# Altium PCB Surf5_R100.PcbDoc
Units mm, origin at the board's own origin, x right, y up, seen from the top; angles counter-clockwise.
Board outline 75 x 21 mm, 4 copper layers (Top Layer, Internal Plane 1, Internal Plane 2, Bottom Layer), stack 0.603 mm thick; 72 components, 94 nets, 353 pads, 156 vias.
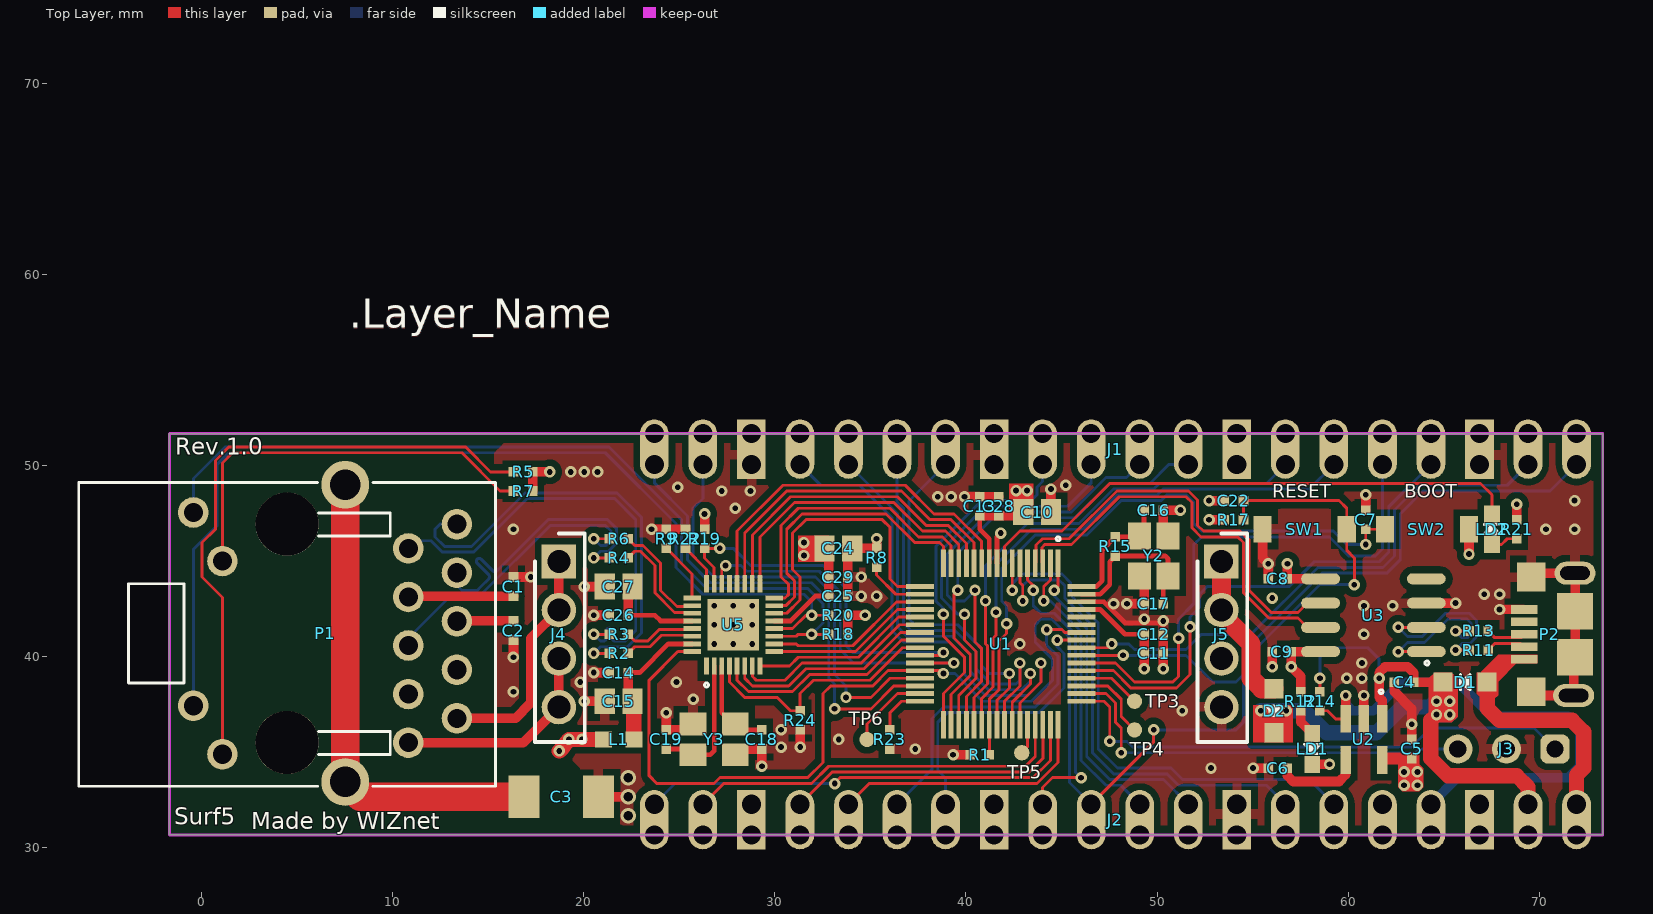
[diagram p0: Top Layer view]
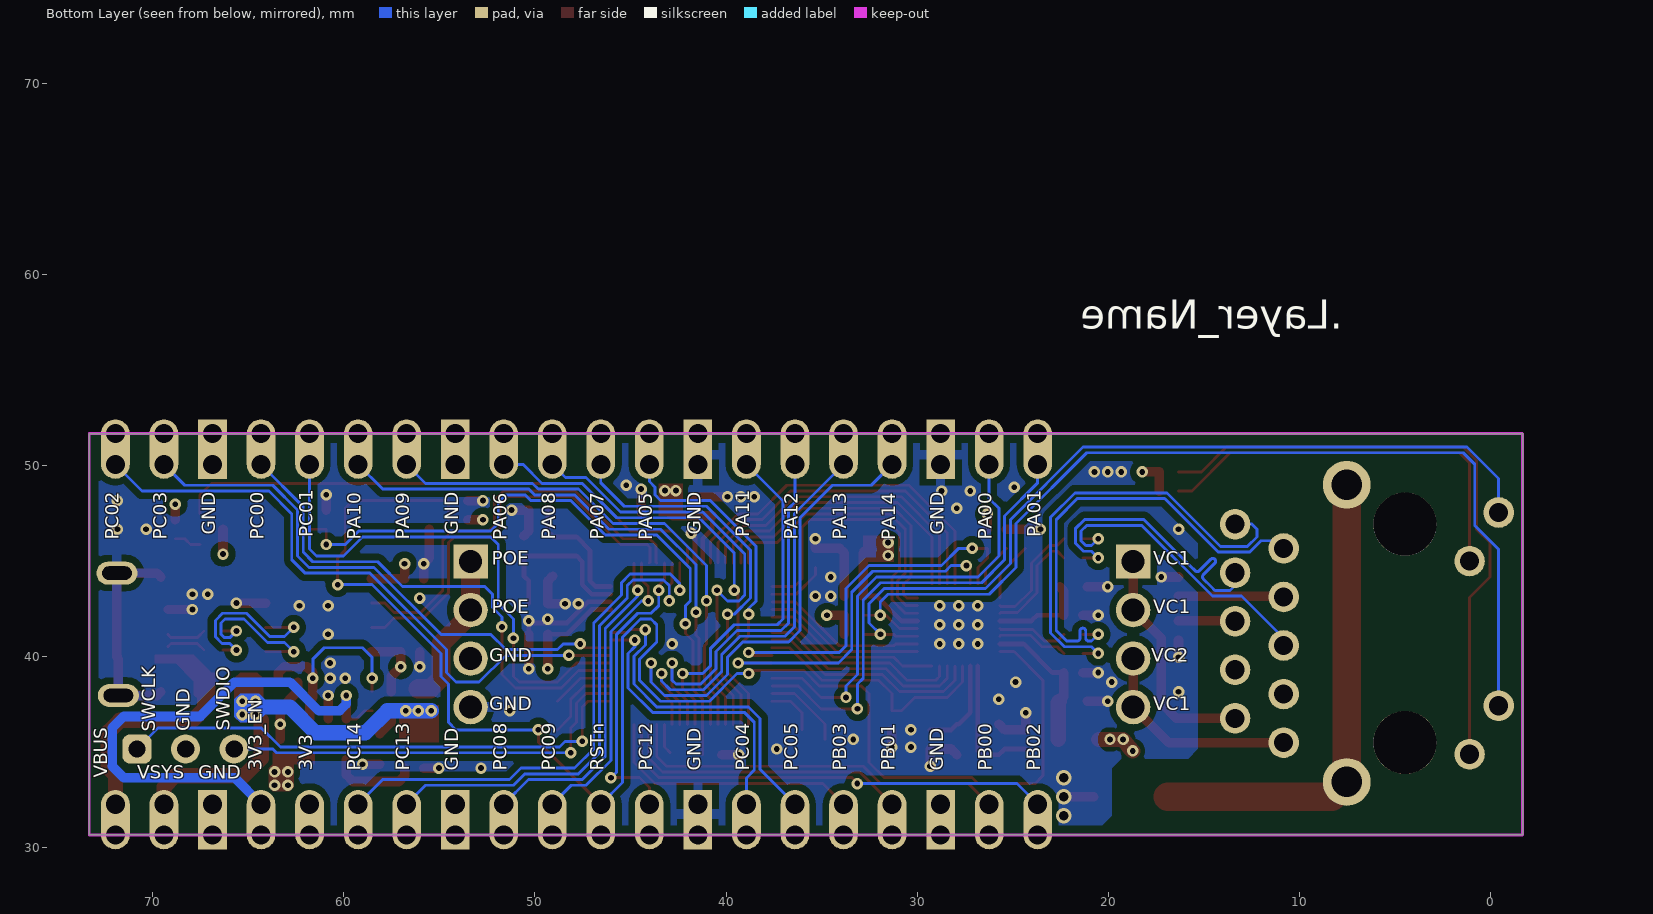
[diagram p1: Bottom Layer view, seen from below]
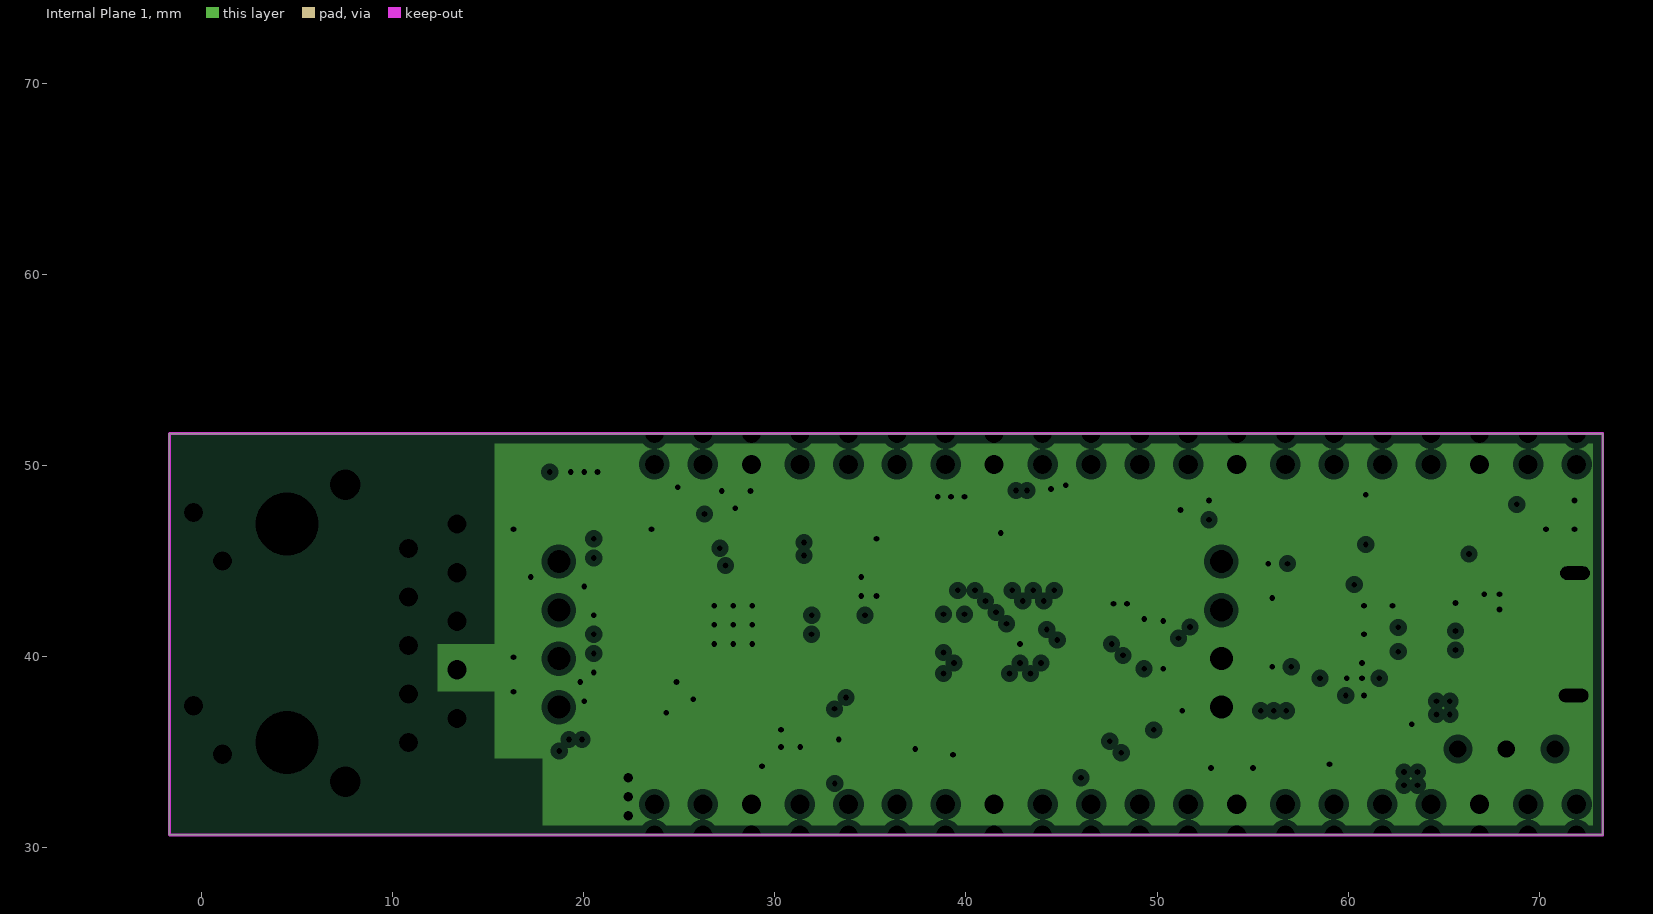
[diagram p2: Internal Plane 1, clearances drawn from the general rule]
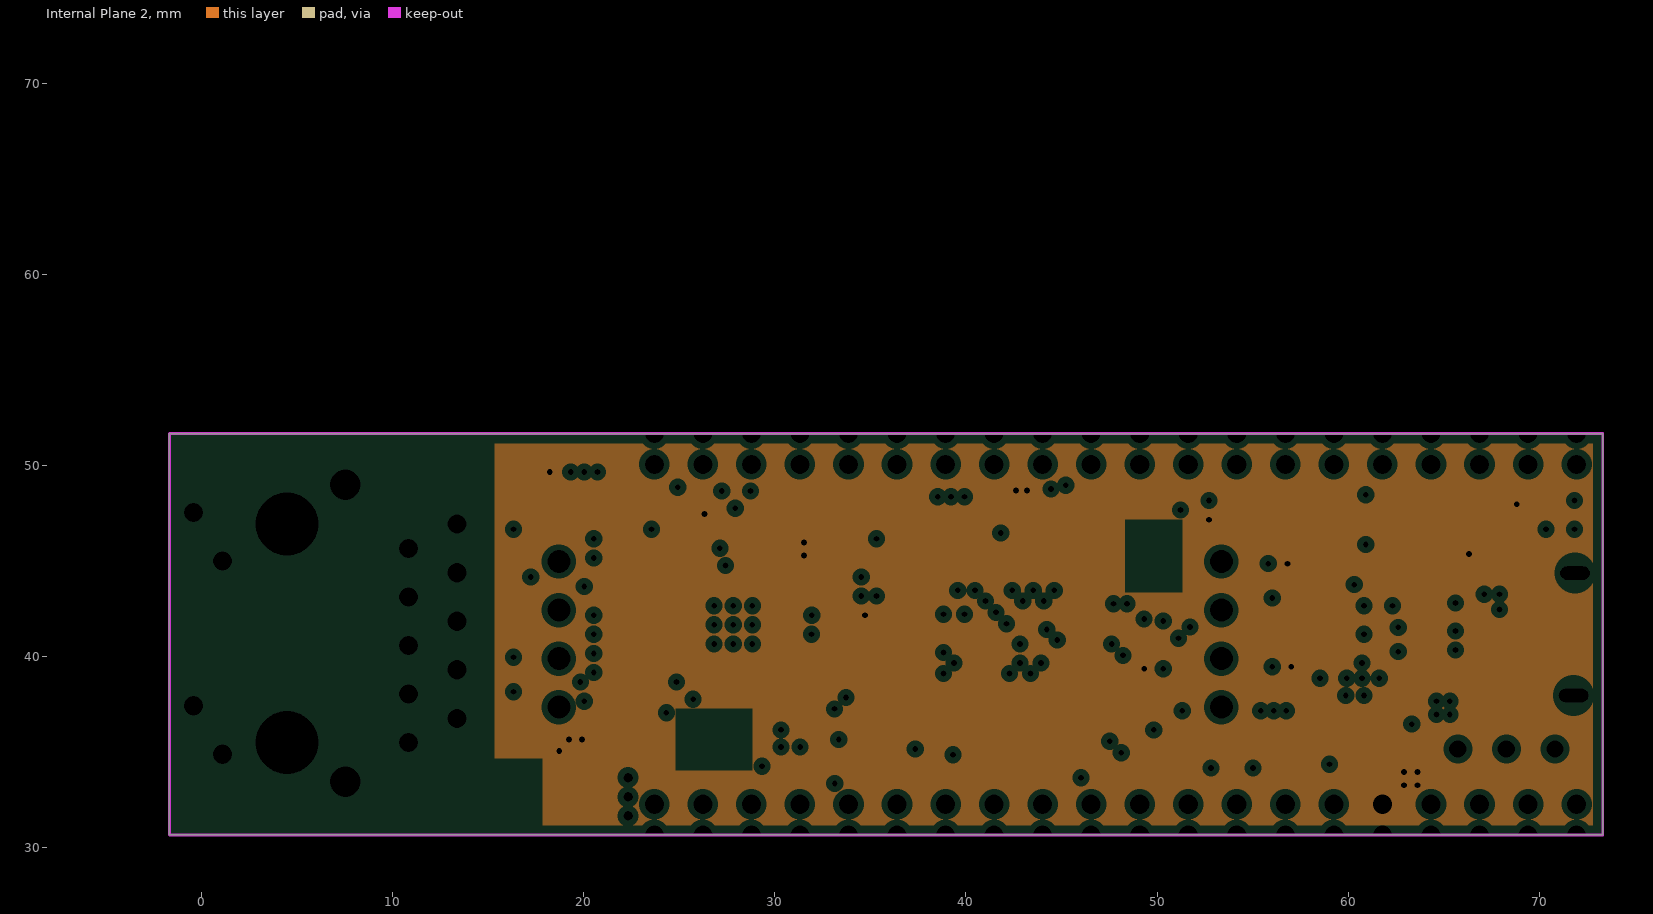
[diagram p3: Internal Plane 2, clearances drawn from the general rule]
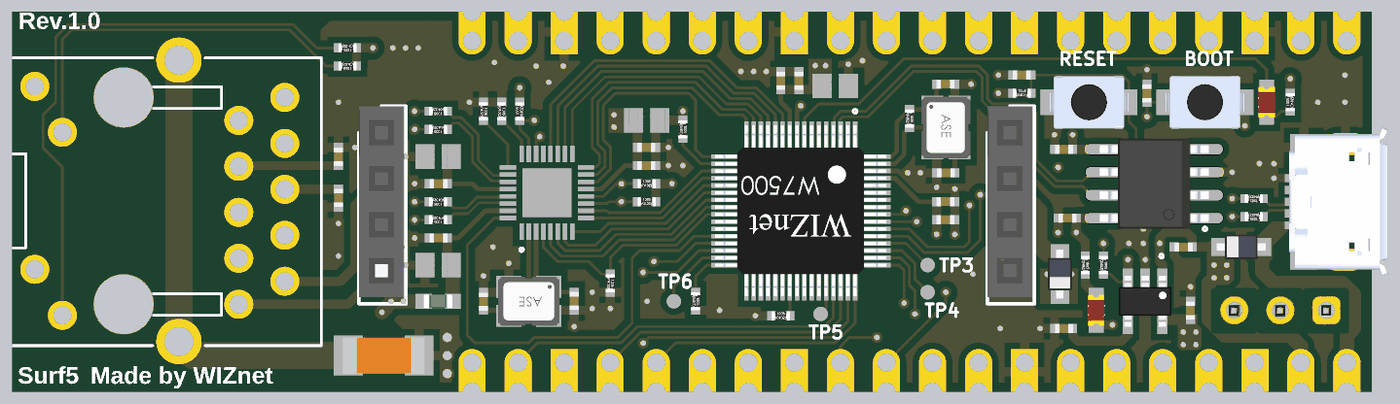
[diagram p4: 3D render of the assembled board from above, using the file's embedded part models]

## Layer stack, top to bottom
Top Solder: solder mask 0.0102, Solder Resist, Dk 3.5
Top Layer: signal copper 0.0356
Dielectric 1: prepreg 0.0711, PP-006, Dk 4.1
Internal Plane 1: plane copper 0.035, net GND
Dielectric1: prepreg 0.32, FR-4, Dk 4.8
Internal Plane 2: plane copper 0.035, net VDD_3.3V
Dielectric 2: prepreg 0.0711, PP-006, Dk 4.1
Bottom Layer: signal copper 0.0356
Bottom Solder: solder mask 0.0102, Solder Resist, Dk 3.5

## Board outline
-1.675,30.65 73.325,30.65 73.325,51.65 -1.675,51.65

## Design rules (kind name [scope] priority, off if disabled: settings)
BoardOutlineClearance [All] p1: gap=0.5 ignorepadtopadclearanceinfootprint=FALSE
Clearance [All] p1: gap=0.15 ignorepadtopadclearanceinfootprint=FALSE except(0.35: Arc-Poly Track-Poly SMDPad-Poly THPad-Poly Via-Poly Fill-Poly Poly-Poly Poly-Region Poly-Text Poly-Hole)
DiffPairsRouting [All] p1: maxlimit=0.15 minlimit=0.15 mostfreqgap=0.15 toplayer_minwidth=0.15 toplayer_maxwidth=0.15 toplayer_prefwidth=0.15 bottomlayer_minwidth=0.15 bottomlayer_maxwidth=0.15 bottomlayer_prefwidth=0.15 maxuncoupledlength=15.24
HoleSize [All] p1: absolutevalues=TRUE maxlimit=4.064 minlimit=0.025 maxpercent=80.000 minpercent=20.000
PlaneClearance [All] p1: clearance=0.3
PlaneConnect [All] p1: planeconnectstyle=Direct reliefexpansion=0.508 reliefentries=4 reliefconductorwidth=0.254 reliefairgap=0.254
PolygonConnect [All] p1: thpad.connectstyle=Relief thpad.reliefconductorwidth=0.5 thpad.reliefentries=4 thpad.polygonreliefangle="90 Angle" thpad.airgapwidth=0.35 smdpad.connectstyle=Relief smdpad.reliefconductorwidth=0.5 smdpad.reliefentries=4 smdpad.polygonreliefangle="90 Angle" smdpad.airgapwidth=0.35 via.connectstyle=Direct via.reliefconductorwidth=0.6 via.reliefentries=4 via.polygonreliefangle="45 Angle" via.airgapwidth=0.35
RoutingVias [All] p1: holewidth=0.3 width=0.6 viastyle="Through Hole" minholewidth=0.3 minwidth=0.6 maxholewidth=0.5 maxwidth=0.8
SolderMaskExpansion [All] p1: expansion=0 istentingtop=FALSE
Width [All] p1: maxlimit=3 minlimit=0.1 preferedwidth=0.15
26 further rules are at their usual default settings.

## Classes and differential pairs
differential pair NewDifferentialPair2: +U_RXD2 -U_TXD2
differential pair NewDifferentialPair1: +NetP2_2 -NetP2_3
differential pair USB_D: +USB_D_P -USB_D_N
differential pair MDI_T: +MDI_T_P -MDI_T_N
differential pair MDI_R: +MDI_R_P -MDI_R_N
differential pair MDI0_T: +MDI0_T_P -MDI0_T_N
differential pair MDI0_R: +MDI0_R_P -MDI0_R_N

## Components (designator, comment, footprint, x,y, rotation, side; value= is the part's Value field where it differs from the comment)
C1 "0.1uF" CAP-0402 16.325,43.65 r270 top
C2 "0.1uF" CAP-0402 16.325,41.35 r90 top
C3 "1nF/2kV" CAP-1808 18.825,32.65 r180 top
C4 "1uF" CAP-0402 62.925,38.65 r0 top
C5 "1uF" CAP-0402 63.325,35.15 r270 top
C6 "0.1uF" CAP-0402 56.325,34.15 r0 top
C7 "0.1uF" CAP-0402 60.925,47.15 r270 top
C8 "0.1uF" CAP-0402 56.325,44.05 r0 top
C9 "0.1uF" CAP-0402 56.525,40.25 r0 top
C10 "10uF/10V" CAP-0805-3 43.725,47.55 r180 top
C11 "0.1uF" CAP-0402 49.825,40.15 r180 top
C12 "0.1uF" CAP-0402 49.825,41.15 r180 top
C13 "0.1uF" CAP-0402 40.725,47.85 r270 top
C14 "0.1uF" CAP-0402 21.825,39.15 r0 top
C15 "10uF/10V" CAP-0805-3 21.825,37.65 r0 top
C16 "30pF" CAP-0402 49.825,47.65 r180 top
C17 "30pF" CAP-0402 49.825,42.75 r0 top
C18 "27pF" CAP-0402 29.325,35.65 r90 top
C19 "27pF" CAP-0402 24.325,35.65 r270 top
C22 "0.1uF" CAP-0402 54.025,48.15 r180 top
C24 "10uF/10V" CAP-0805-3 33.325,45.65 r180 top
C25 "0.1uF" CAP-0402 33.325,43.15 r180 top
C26 "0.1uF" CAP-0402 21.825,42.15 r0 top
C27 "10uF/10V" CAP-0805-3 21.825,43.65 r0 top
C28 "0.1uF" CAP-0402 41.725,47.85 r270 top
C29 "0.1uF" CAP-0402 33.325,44.15 r180 top
D1 "BAT60A" SOD-323(1-C,2-A) 66.125,38.65 r0 top
D2 "BAT60A" SOD-323(1-C,2-A) 56.125,37.15 r90 top
J1 "2.54mm 1x20 Pin Header DIP" IDC-1X20 71.955,50.04 r180 top locked
J2 "2.54mm 1x20 Pin Header DIP" IDC-1X20 23.695,32.26 r0 top locked
J3 "2.54mm 1x3 Pin Header DIP" IDC-1X3 70.825,35.15 r180 top
J4 "Header Socket 1x4_2.54mm" Header-Socket(DIP)_4x1_2.54mm 18.7,44.96 r270 top locked
J5 "Header Socket 1x4_2.54mm" Header-Socket(DIP)_4x1_2.54mm 53.369,44.96 r270 top locked
L1 "HH-1M1608-121JT" IND-0603 21.825,35.65 r0 top
LD1 "Red" LED-0603-RED 58.125,35.15 r270 top
LD2 "Green" LED-0603-RED 67.525,46.65 r90 top locked
P1 "RB1-ZZ-0049" RB1-ZZ-0049 4.475,41.2 r270 top
P2 "Micro USB" "Micro 5P B DBX 6.4" 73.325,41.15 r180 top locked
R1 "4.7K" RES-0402 40.725,34.85 r0 top
R2 "3.3R" RES-0402 21.825,40.15 r180 top
R3 "3.3R" RES-0402 21.825,41.15 r180 top
R4 "3.3R" RES-0402 21.825,45.15 r180 top
R5 "330R" RES-0402 16.825,49.65 r180 top
R6 "3.3R" RES-0402 21.825,46.15 r180 top
R7 "330R" RES-0402 16.825,48.65 r180 top
R8 "4.7K" RES-0402 35.325,45.15 r270 top
R9 "6.19K/1%" RES-0402 24.325,46.15 r270 top
R11 "3R3" RES-0402 66.825,40.325 r180 top
R12 "470R" RES-0402 57.525,37.65 r270 top
R13 "3R3" RES-0402 66.825,41.325 r180 top
R14 "100K" RES-0402 58.525,37.65 r270 top
R15 "1M" RES-0402 47.825,45.75 r270 top
R17 "4.7K" RES-0402 54.025,47.15 r0 top
R18 "5.1K" RES-0402 33.325,41.15 r0 top
R19 "5.1K" RES-0402 26.325,46.15 r90 top
R20 "5.1K" RES-0402 33.325,42.15 r0 top
R21 "330R" RES-0402 68.825,46.65 r90 top
R22 "5.1K" RES-0402 25.325,46.15 r270 top
R23 "4.7K" RES-0402 36.025,35.65 r270 top
R24 "5.1K" RES-0402 31.325,36.65 r270 top
SW1 "DJT-1115VNS" 1185A 57.725,46.65 r0 top
SW2 "DJT-1115VNS" 1185A 64.125,46.65 r180 top
TP3 "TPS" TPS 48.825,37.65 r270 top
TP4 "TPS" TPS 48.825,36.15 r270 top
TP5 "TPS" TPS 42.925,34.95 r270 top
TP6 "TPS" TPS 34.825,35.65 r270 top
U1 "W7500" W7500-LQFP64 41.825,40.65 r270 top locked
U2 "LM8805SF5-33V" SOT-23-5L 60.825,35.65 r270 top
U3 "USB to Uart" CH340N 61.325,42.15 r90 top
U5 "IP101GR/GRI" QFN32(0.4/4X4) 27.825,41.65 r90 top
Y2 "12MHz" OSC-TZ1067B 49.825,45.25 r270 top
Y3 "25MHz" OSC-82J0626 26.825,35.65 r180 top

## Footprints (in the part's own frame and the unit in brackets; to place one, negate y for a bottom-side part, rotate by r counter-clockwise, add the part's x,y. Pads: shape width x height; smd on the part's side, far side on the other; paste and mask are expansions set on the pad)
1185A [mm]
  rect 0.95x1.4 smd: 1(-2.2,0) 2(2.2,0)
  body extent -2.18,-1.45 2.18,1.45, height 1.7
CAP-0402 [mm]
  rect 0.5x0.5 smd: 1(-0.5,0) 2(0.5,0)
  body extent -0.48,-0.25 0.52,0.25, height 0.6
CAP-0805-3 [mm]
  rect 1.055x1.356 smd paste+0 mask+0: 1(-0.726,0) 2(0.726,0)
  body extent -1.35,-0.82 1.35,0.82, height 0.25
CAP-1808 [mm] "Ceramic CAP 1808(4520)"
  rect 1.6x2.2 smd: 1(-1.95,0) 2(1.95,0)
  body extent -2.25,-1.02 2.25,1.01, height 2
CH340N [mm]
  oval 0.574x2.036 smd paste+0 mask+0.051: 1(-1.905,-2.768) 2(-0.635,-2.768) 3(0.635,-2.768) 4(1.905,-2.768) 5(1.905,2.768) 6(0.635,2.768) 7(-0.635,2.768) 8(-1.905,2.768)
  body extent -2.5,-3.01 2.5,3.01, height 1.75
Header-Socket(DIP)_4x1_2.54mm [mm]
  rect 1.8x1.8 hole 1.2: 1(0,0)
  round 1.8 hole 1.2: 2(2.54,0) 3(5.08,0) 4(7.62,0)
  silkscreen extent -1.47,-1.25 9.44,1.35, body extent -1.47,-1.25 9.09,1.25, height 8.65
IDC-1X3 [mil]
  rrect50% 60x60 hole 36: 1(0,0)
  round 60 hole 36: 2(100,0) 3(200,0)
  body extent -49,-49 251,51, height 336
IDC-1X20 [mm]
  oval 1.5x2.5 hole 1 copper offset 0,-0.5: 1(0,0) 2(2.54,0) 4(7.62,0) 5(10.16,0) 6(12.7,0) 7(15.24,0) 9(20.32,0) 10(22.86,0) 11(25.4,0) 12(27.94,0) 14(33.02,0) 15(35.56,0) 16(38.1,0) 17(40.64,0) 19(45.72,0) 20(48.26,0)
  oval 1.5x2.5 hole 1 copper offset 0,0.5: 1(0,-1.61) 2(2.54,-1.61) 4(7.62,-1.61) 5(10.16,-1.61) 6(12.7,-1.61) 7(15.24,-1.61) 9(20.32,-1.61) 10(22.86,-1.61) 11(25.4,-1.61) 12(27.94,-1.61) 14(33.02,-1.61) 15(35.56,-1.61) 16(38.1,-1.61) 17(40.64,-1.61) 19(45.72,-1.61) 20(48.26,-1.61)
  rect 1.5x2.5 hole 1 copper offset 0,0.5: 3(5.08,-1.61) 8(17.78,-1.61) 13(30.48,-1.61) 18(43.18,-1.61)
  rect 1.5x2.5 hole 1 copper offset 0,-0.5: 3(5.08,0) 8(17.78,0) 13(30.48,0) 18(43.18,0)
IND-0603 [mm] "Inductor 0603(1608)"
  rect 0.89x0.82 smd: 1(-0.8,0) 2(0.8,0)
  body extent -0.8,-0.4 0.8,0.4, height 0.95
LED-0603-RED [mm] "LED-0603-RED"
  rect 0.89x0.82 smd: 1(-0.8,0) 2(0.8,0)
  body extent -0.85,-0.45 0.85,0.45, height 0.9
"Micro 5P B DBX 6.4" [mm]
  rect 1.38x0.45 smd: 1(4.11,1.3) 2(4.11,0.65) 3(4.11,0) 4(4.11,-0.65) 5(4.11,-1.3)
  oval 2.15x1.2 hole 0.7 slot 1.55 at 0 deg: 6(1.524,3.2) 7(1.45,-3.2)
  rect 1.9x1.9 smd: 8(1.45,1.2) 9(1.45,-1.2)
  rect 1.5x1.5 smd: 10(3.75,-3) 11(3.75,3)
  body extent -0.88,-4.1 4.55,4.1, height 2.68
OSC-82J0626 [mm]
  rect 1.4x1.2 smd: 1(-1.1,-0.8) 2(1.1,-0.8) 3(1.1,0.8) 4(-1.1,0.8)
  body extent -1.7,-1.35 1.7,1.35, height 1.06
OSC-TZ1067B [mm]
  rect 1.4x1.2 smd: 1(-1.05,-0.75) 2(1.05,-0.75) 3(1.05,0.75) 4(-1.05,0.75)
  body extent -1.7,-1.35 1.7,1.35, height 1.06
QFN32(0.4/4X4) [mm]
  rect 0.9x0.25 smd: 1(-2.15,1.4) 2(-2.15,1) 3(-2.15,0.6) 4(-2.15,0.2) 5(-2.15,-0.2) 6(-2.15,-0.6) 7(-2.15,-1) 8(-2.15,-1.4) 17(2.15,-1.4) 18(2.15,-1) 19(2.15,-0.6) 20(2.15,-0.2) 21(2.15,0.2) 22(2.15,0.6) 23(2.15,1) 24(2.15,1.4)
  rect 0.25x0.9 smd: 9(-1.4,-2.15) 10(-1,-2.15) 11(-0.6,-2.15) 12(-0.2,-2.15) 13(0.2,-2.15) 14(0.6,-2.15) 15(1,-2.15) 16(1.4,-2.15) 25(1.4,2.15) 26(1,2.15) 27(0.6,2.15) 28(0.2,2.15) 29(-0.2,2.15) 30(-0.6,2.15) 31(-1,2.15) 32(-1.4,2.15)
  rect 2.7x2.7 smd: 33(0,0)
  silkscreen extent -3.25,1.3 -3.05,1.5, body extent -2.1,-2.1 2.1,2.1, height 0.76
RB1-ZZ-0049 [mm]
  round 3.3 hole 3.3: 0(-5.715,0) 0(5.715,0)
  round 1.6 hole 1: L1(6.325,-3.38) L2(3.785,-4.9) L3(-3.785,-3.38) L4(-6.325,-4.9) R1(-5.715,8.89) R2(-4.445,6.35) R3(-3.175,8.89) R4(-1.905,6.35) R5(-0.635,8.89) R6(0.635,6.35) R7(1.905,8.89) R8(3.175,6.35) R9(4.445,8.89) R10(5.715,6.35)
  round 2.5 hole 1.6: S1(-7.775,3.05) S2(7.775,3.05)
  Top Layer pour cut-out: -6.3,1.65 -6.3,5.4 -5.1,5.4 -5.1,1.65
  Top Layer pour cut-out: 5.13,1.65 5.13,5.4 6.33,5.4 6.33,1.65
  Top Layer pour cut-out: -2.6,-8.3 -2.6,-5.4 2.6,-5.4 2.6,-8.3
  Top Layer pour cut-out: -8.8,-7.6 8.8,-7.6 8.8,-4.6 -8.8,-4.6
  silkscreen extent -7.9,-10.9 8,10.9, body extent -7.9,-10.9 8,10.9, height 13.35
RES-0402 [mm]
  rect 0.5x0.5 smd: 1(-0.5,0) 2(0.5,0)
  body extent -0.5,-0.25 0.5,0.25, height 0.35
SOD-323(1-C,2-A) [mm]
  rect 1x1 smd: 1(-1.15,0) 2(1.15,0)
  body extent -1.35,-0.67 1.35,0.68, height 0.79
SOT-23-5L [mm]
  rect 1.45x0.55 smd: 1(-1.075,0.95) 2(-1.075,0) 3(-1.075,-0.95) 4(1.075,-0.95) 5(1.075,0.95)
  body extent -1.4,-1.45 1.4,1.45, height 1.45
TPS [mm]
  round 0.8 smd: 1(0,0)
W7500-LQFP64 [mm]
  rect 1.45x0.25 smd: 1(-4.225,3) 2(-4.225,2.6) 3(-4.225,2.2) 4(-4.225,1.8) 5(-4.225,1.4) 6(-4.225,1) 7(-4.225,0.6) 8(-4.225,0.2) 9(-4.225,-0.2) 10(-4.225,-0.6) 11(-4.225,-1) 12(-4.225,-1.4) 13(-4.225,-1.8) 14(-4.225,-2.2) 15(-4.225,-2.6) 16(-4.225,-3) 33(4.225,-3) 34(4.225,-2.6) 35(4.225,-2.2) 36(4.225,-1.8) 37(4.225,-1.4) 38(4.225,-1) 39(4.225,-0.6) 40(4.225,-0.2) 41(4.225,0.2) 42(4.225,0.6) 43(4.225,1) 44(4.225,1.4) 45(4.225,1.8) 46(4.225,2.2) 47(4.225,2.6) 48(4.225,3)
  rect 0.25x1.45 smd: 17(-3,-4.225) 18(-2.6,-4.225) 19(-2.2,-4.225) 20(-1.8,-4.225) 21(-1.4,-4.225) 22(-1,-4.225) 23(-0.6,-4.225) 24(-0.2,-4.225) 25(0.2,-4.225) 26(0.6,-4.225) 27(1,-4.225) 28(1.4,-4.225) 29(1.8,-4.225) 30(2.2,-4.225) 31(2.6,-4.225) 32(3,-4.225) 49(3,4.225) 50(2.6,4.225) 51(2.2,4.225) 52(1.8,4.225) 53(1.4,4.225) 54(1,4.225) 55(0.6,4.225) 56(0.2,4.225) 57(-0.2,4.225) 58(-0.6,4.225) 59(-1,4.225) 60(-1.4,4.225) 61(-1.8,4.225) 62(-2.2,4.225) 63(-2.6,4.225) 64(-3,4.225)
  body extent -4.73,-4.74 4.73,4.72, height 1

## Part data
C1 C2 C4 C5 C6 C7 C8 C9 C11 C12 C13 C14 C16 C17 C18 C19 C22 C25 C26 C28 C29: library part CAP-0402, "Ceramic CAP 0402(1005)"
C3: library part CAP-1808, "Ceramic CAP 1808(4520)"
C10 C15 C24 C27: library part CAP-0805, "MLCC-0805(2012)"
D1 D2: library part DIODE-BAT60A, "Silicon Schottky Diode"
J4 J5: "Connector", Manufacturer_Name=Harwin, Manufacturer_Part_Number=M20-7820442, Mouser Part Number=855-M20-7820442
L1: library part IND-0603, "Inductor 0603(1608)"
LD1 LD2: library part LED-0603, "LED-0603"
P1: "PoE RJ45"
P2: library part "Micro USB 5P DBX6.4", "Micro USB B Connector SMD"
R1 R2 R3 R4 R5 R6 R7 R8 R9 R11 R12 R13 R14 R15 R17 R18 R19 R20 R21 R22 R23 R24: library part RES-0402, "RES-0402"
SW1 SW2: library part ITS-1107(SMD), "TACT Switch (SMD)"
TP3 TP4 TP5 TP6: "Test_point", Contact Resistance=20mOhm, Manufacturer="Wurth Elektronik", Operating Temperature=-40to105degC, Package Reference=61300211121, Rated Current=3A, Withstanding Voltage=500VAC, Working Voltage=250VAC
U1: "WIZnet ARM Cortex-M0"
U2: "600mA CMOS LDO Regulator"
U3: library part CH340N
Y2: library part OSC-TZ1067B-12MHz, "X-tal 12MHz,3.2x2.5 SMD, CL=20pF"
Y3: library part OSC-82J0626-25MHz, "X-tal 25MHz,3.2x2.5 SMD, CL=18pF"

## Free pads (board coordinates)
  round 0 on Mech16 paste+0 mask+0: 1(73.875,71.375)

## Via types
v1: diameter 0.6, hole 0.3, Top Layer to Bottom Layer, tented both sides, 153 vias
v2: diameter 0.8, hole 0.5, Top Layer to Bottom Layer, tented both sides, 3 vias

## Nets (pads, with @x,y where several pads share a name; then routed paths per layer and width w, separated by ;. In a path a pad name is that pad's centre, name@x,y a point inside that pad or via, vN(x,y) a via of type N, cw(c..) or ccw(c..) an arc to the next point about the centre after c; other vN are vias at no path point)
3V3_EN: J2.17 R14.2 U2.3 | length 27.8
  Top Layer w0.15: R14.2 58.925,37.15 59.35,36.725 U2.3
  Top Layer w0.5: U2.3 v1(59.875,37.95)
  Bottom Layer w0.5: v1(59.875,37.95) 59.875,37.5 60.225,37.15 61.325,37.15 62.825,38.65 65.725,38.65 67.525,36.85 71.525,36.85 72.125,36.25 72.125,34.25 71.525,33.65 65.725,33.65 J2.17@64.335,32.26
BOOT: C7.2 R1.2 SW2.2 U1.39 | length 34.4
  Top Layer w0.15: R1.2 U1.39 41.225,37.75 41.725,38.25 41.725,40.8 42.125,41.2 v1(42.125,41.7) ; v1(60.925,45.85) C7.2 SW2.2
  Bottom Layer w0.15: v1(42.125,41.7) 42.125,42.65 41.875,42.9 41.875,44.6 43.625,46.35 46.325,46.35 48.125,48.15 50.225,48.15 50.525,48.45 51.525,48.45 51.925,48.05 51.925,46.95 52.325,46.55 59.225,46.55 59.925,45.85 v1(60.925,45.85)
CH_GND: C3.2 P1.S1 P1.S2 | length 25.2
  Top Layer w1.5: P1.S1 P1.S2 8.3,32.65 C3.2
COL: R24.1 U1.25 U5.4 | length 13.3
  Top Layer w0.15: U5.4 27.625,38.65 28.425,37.85 30.125,37.85 30.825,37.15 R24.1 31.325,38.05 32.025,38.75 34.975,38.75 36.675,40.45 U1.25
CRS: U1.11 U5.20 | length 18.9
  Top Layer w0.15: U5.20 28.025,46.55 30.425,48.95 36.825,48.95 38.325,47.45 39.375,47.45 40.825,46 U1.11
GND: C1.1 C2.1 C3.1 C4.1 C5.1 C6.1 C7.1 C8.1 C9.1 C10.1 C11.1 C12.1 C13.1 C14.1 C15.1 C16.1 C17.1 C18.1 C19.1 C22.2 C24.1 C25.1 C26.1 C27.1 C28.1 C29.1 J1.3 J1.8 J1.13 J1.18 J2.3 J2.8 J2.13 J2.18 J3.2 J5.3 J5.4 LD1.2 P1.R7 P2.5 P2.6 P2.7 P2.8 P2.9 P2.10 P2.11 R1.1 R8.1 R9.1 R22.1 R23.2 R24.2 SW1.1 U1.9 U1.62 U2.2 U3.3 U5.33 Y2.2 Y2.4 Y3.2 Y3.4 | length 61.8
  Top Layer w0.25: U1.9 41.625,46.25 v1(41.825,46.45) ; U1.62 47.225,42.85 48.325,41.75 50.125,41.75 50.325,41.55 C12.1
  Top Layer w0.45: v1(67.925,42.45) P2.5
  Top Layer w0.5: v1(16.325,39.95) C2.1 ; C1.1 v1(17.225,44.15) ; v1(20.025,37.65) C15.1 ; v1(20.025,43.65) C27.1 ; v1(20.525,39.15) C14.1 ; v1(20.525,42.15) C26.1 ; C3.1 v2(22.325,32.65) ; v1@23.525,46.65 v1(23.55,46.65) R9.1 R22.1 ; v1(24.325,37.05) C19.1 25.425,36.15 Y3.2 ; Y3.4 28.225,35.15 C18.1 v1(29.325,34.25) ; v1(31.325,35.25) R24.2 ; C25.1 C29.1 33.825,45.424 C24.1 R8.1 v1(35.325,46.15) ; v1(39.325,34.85) R1.1 ; v1(39.925,48.35) C13.1 C28.1 ; C10.1 v1(44.451,48.75) ; v1(48.425,42.75) C17.1 49.325,43.95 Y2.2 ; v1(50.325,39.35) C11.1 C12.1 ; Y2.4 50.325,46.55 C16.1 v1(51.225,47.65) ; v1(52.725,48.15) C22.2 ; v1(55.025,34.15) C6.1 ; SW1.1 55.525,45.15 v1(55.825,44.85) C8.1 ; v1(56.025,39.45) C9.1 ; LD1.2 v1(59.025,34.35) ; U2.2 v1(60.825,37.95) ; C7.1 v1(60.925,48.45) ; C4.1 62.425,38.15 63.325,37.25 v1(63.325,36.45) C5.1 ; U3.3 v1(65.625,42.785) ; P2.11 69.775,37.95 P2.6 71.801,39.876 P2.8 P2.9 P2.7 69.775,44.35 P2.10
  other v1: 52.825,34.15 37.35,35.15 30.325,35.25 33.35,35.65 30.325,36.15 51.325,37.15 25.725,37.75 16.325,38.15 19.825,38.65 24.85,38.65 59.925,38.85 60.725,38.85 60.725,39.65 26.825,40.65 27.825,40.65 28.825,40.65 42.825,40.65 60.825,41.15 26.825,41.65 27.825,41.65 28.825,41.65 50.325,41.85 49.325,41.95 26.825,42.65 27.825,42.65 28.825,42.65 60.825,42.65 62.325,42.65 47.725,42.75 56.025,43.05 34.525,43.15 35.325,43.15 67.125,43.25 67.925,43.25 34.525,44.15 16.325,46.65 70.35,46.65 71.85,46.65 27.925,47.75 71.85,48.15 38.525,48.35 39.225,48.35 27.225,48.65 28.725,48.65 24.925,48.85 45.225,48.95 19.325,49.65 20.025,49.65 20.725,49.65
  other v2: 22.325,31.65 22.325,33.65
LED_0: P1.L4 R18.1 U5.11 | length 44.9
  Top Layer w0.15: U5.11 31.125,41.05 31.225,41.15 v1(31.925,41.15) R18.1
  Bottom Layer w0.15: P1.L4 -0.425,49.3 1.225,50.95 21.325,50.95 25.125,47.15 25.125,44.85 26.425,43.55 31.725,43.55 32.525,42.75 32.525,41.75 v1(31.925,41.15)
LED_3: P1.L2 R20.1 U5.12 | length 52.9
  Top Layer w0.15: U5.12 30.925,41.45 31.618,42.143 v1(31.932,42.143) 31.925,42.15 R20.1
  Bottom Layer w0.15: P1.L2 -0.425,45.6 0.825,46.85 0.825,50.05 1.425,50.65 21.125,50.65 24.825,46.95 24.825,44.65 26.225,43.25 31.525,43.25 31.932,42.843 v1(31.932,42.143)
MDC: U1.27 U5.22 | length 18.6
  Top Layer w0.15: U5.22 27.225,44.55 v1(27.425,44.75) ; U1.27 v1(39.375,39.65)
  Bottom Layer w0.15: v1(27.425,44.75) 28.225,44.75 28.525,44.45 32.325,44.45 33.425,43.35 33.425,40.35 34.125,39.65 v1(39.375,39.65)
MDI0_R_N: R6.1 U5.26 | length 5.7
  Top Layer w0.15: R6.1 22.675,45.8 23.099,45.8 24.025,44.874 24.025,43.45 24.875,42.6 25.625,42.6 U5.26
MDI0_R_P: R4.1 U5.27 | length 5.7
  Top Layer w0.15: R4.1 22.675,45.5 22.975,45.5 23.725,44.75 23.725,43.326 24.751,42.3 25.625,42.3 U5.27
MDI0_T_N: R3.1 U5.29 | length 3.8
  Top Layer w0.15: R3.1 22.675,40.8 23.351,40.8 23.951,41.4 25.625,41.4 U5.29
MDI0_T_P: R2.1 U5.30 | length 3.8
  Top Layer w0.15: R2.1 22.675,40.5 23.475,40.5 24.075,41.1 25.625,41.1 U5.30
MDI_R_N: P1.R6 R6.2 | length 16
  Top Layer w0.15: v1(20.525,46.15) R6.2
  Bottom Layer w0.15: P1.R6 10.825,40.95 13.025,43.15 14.549,43.15 18.249,46.85 21.125,46.85 21.425,46.55 21.425,46.05 21.175,45.8 20.875,45.8 v1(20.525,46.15)
MDI_R_P: P1.R3 R4.2 | length 16
  Top Layer w0.15: v1(20.525,45.15) R4.2
  Bottom Layer w0.15: P1.R3 13.365,43.71 13.625,43.45 14.425,43.45 14.6,43.625 15.027,44.052 ccw(c14.921,44.158) 15.027,44.264 14.425,44.867 cw(c14.531,44.973) 14.425,45.079 cw(c14.531,44.973) 14.637,45.079 15.239,44.476 ccw(c15.345,44.582) 15.451,44.476 15.717,44.742 18.125,47.15 21.249,47.15 21.725,46.674 21.725,45.926 21.299,45.5 20.875,45.5 v1(20.525,45.15)
MDI_T_N: P1.R2 R3.2 | length 24.2
  Top Layer w0.15: v1(20.525,41.15) R3.2
  Bottom Layer w0.15: P1.R2 11.23,46.05 12.001,46.05 12.601,45.45 14.249,45.45 17.049,48.25 21.625,48.25 22.725,47.15 22.725,41.35 22.175,40.8 22.006,40.8 21.631,40.8 cw(c21.631,40.95) 21.481,40.95 21.481,41.325 ccw(c21.331,41.325) 21.181,41.325 21.181,40.95 cw(c21.031,40.95) 21.031,40.8 20.875,40.8 20.625,41.05 v1(20.525,41.15)
MDI_T_P: P1.R1 R2.2 | length 24.1
  Top Layer w0.15: v1(20.525,40.15) R2.2
  Bottom Layer w0.15: P1.R1 12.49,46.915 12.225,46.65 12.225,46.25 12.725,45.75 14.125,45.75 16.925,48.55 21.749,48.55 23.025,47.274 23.025,41.226 22.299,40.5 20.875,40.5 v1(20.525,40.15)
MDIO: R19.1 U1.26 U5.23 | length 19.9
  Top Layer w0.15: U5.23 26.825,44.65 26.325,45.15 R19.1 v1(27.125,45.65) ; U1.26 38.675,40.05 v1(38.825,40.2)
  Bottom Layer w0.15: v1(27.125,45.65) 27.825,45.65 28.725,44.75 32.525,44.75 33.725,43.55 33.725,40.55 34.075,40.2 v1(38.825,40.2)
NetC1_2: C1.2 P1.R4 | length 5.5
  Top Layer w0.5: P1.R4 10.87,43.15 C1.2
NetC2_2: C2.2 P1.R5 | length 3
  Top Layer w0.5: P1.R5 13.38,41.85 C2.2
NetC6_2: C6.2 U2.4 | length 4.5
  Top Layer w0.5: C6.2 56.825,33.75 57.125,33.45 59.525,33.45 59.875,33.8 U2.4
NetLD1_1: LD1.1 R12.2 | length 1.4
  Top Layer w0.5: R12.2 57.525,36.55 LD1.1
NetLD2_1: LD2.1 R21.1 | length 1.4
  Top Layer w0.15: LD2.1 68.025,45.85 68.325,46.15 R21.1
NetP1_L1: P1.L1 R5.2 | length 32.5
  Top Layer w0.15: P1.L1 1.095,43.08 0.025,44.15 0.025,45.95 0.725,46.65 0.725,50.25 1.425,50.95 13.825,50.95 15.125,49.65 R5.2
NetP1_L3: P1.L3 R7.2 | length 21.4
  Top Layer w0.15: P1.L3 1.095,50.12 1.625,50.65 13.625,50.65 15.625,48.65 R7.2
NetP2_2: P2.2 R11.1 | length 2.1
  Top Layer w0.15: R11.1 67.675,40.675 69.04,40.675 P2.2
NetP2_3: P2.3 R13.1 | length 2.1
  Top Layer w0.15: R13.1 67.675,40.975 69.04,40.975 P2.3
NetR8_2: R8.2 U1.18 | length 3.1
  Top Layer w0.15: R8.2 35.325,44.25 36.325,43.25 U1.18
NetR9_2: R9.2 U5.25 | length 3.2
  Top Layer w0.15: R9.2 25.675,44.3 U5.25
NetR22_2: R22.2 U5.24 | length 2.3
  Top Layer w0.15: R22.2 26.425,44.55 U5.24
NetR23_1: R23.1 U1.32 | length 2.7
  Top Layer w0.15: R23.1 36.025,37.05 36.625,37.65 U1.32
NetTP3_1: TP3.1 U1.52 | length 3.3
  Top Layer w0.15: U1.52 47.625,38.85 TP3.1
NetTP4_1: TP4.1 U1.51 | length 4.3
  Top Layer w0.15: U1.51 47.425,38.45 48.125,37.75 48.125,36.85 TP4.1
NetTP5_1: TP5.1 U1.44 | length 1.6
  Top Layer w0.15: TP5.1 43.225,35.25 U1.44
NetTP6_1: TP6.1 U1.31 | length 4.2
  Top Layer w0.15: TP6.1 34.825,36.45 36.425,38.05 U1.31
PA_00: J1.19 U1.29 | length 24.7
  Top Layer w0.15: v1(33.725,37.85) 35.025,37.85 36.025,38.85 U1.29
  Bottom Layer w0.15: J1.19@26.235,51.65 26.235,50.04 26.235,48.26 25.725,47.75 25.725,45.25 26.825,44.15 32.125,44.15 33.125,43.15 33.125,39.05 33.725,38.45 v1(33.725,37.85)
PA_01: J1.20 U1.30 | length 26.4
  Top Layer w0.15: v1(33.125,37.25) 35.025,37.25 36.225,38.45 U1.30
  Bottom Layer w0.15: J1.20@23.695,51.65 23.695,50.04 23.695,49.08 25.425,47.35 25.425,45.05 26.625,43.85 31.925,43.85 32.825,42.95 32.825,38.85 33.125,38.55 v1(33.125,37.25)
PA_05: J1.12 U1.33 | length 18.5
  Top Layer w0.15: U1.33 38.825,38.05 39.925,39.15 39.925,39.95 38.825,41.05 v1(38.825,42.2)
  Bottom Layer w0.15: v1(38.825,42.2) 38.825,42.5 38.425,42.9 38.425,45.75 40.825,48.15 43.425,48.15 43.725,48.45 43.725,48.85 44.015,49.14 J1.12@44.015,50.04
PA_06: J1.9 U1.34 | length 23.8
  Top Layer w0.15: U1.34 39.225,38 40.225,39 40.225,40.1 39.375,40.95 39.375,43.25 v1(39.575,43.45)
  Bottom Layer w0.15: v1(39.575,43.45) 39.575,45.4 41.425,47.25 45.725,47.25 47.525,49.05 49.625,49.05 50.615,50.04 J1.9@51.635,50.04
PA_07: J1.11 U1.35 | length 20.7
  Top Layer w0.15: U1.35 39.625,37.95 40.525,38.85 40.525,40.25 39.925,40.85 v1(39.925,42.2)
  Bottom Layer w0.15: v1(39.925,42.2) 39.575,42.2 38.725,43.05 38.725,45.55 41.025,47.85 45.325,47.85 46.555,49.08 J1.11@46.555,50.04
PA_08: J1.10 U1.36 | length 23.5
  Top Layer w0.15: U1.36 40.025,37.9 40.825,38.7 40.825,40.4 40.475,40.75 v1(40.475,43.45)
  Bottom Layer w0.15: v1(40.475,43.45) 39.925,42.9 39.325,42.9 39.025,43.2 39.025,45.35 41.225,47.55 45.525,47.55 47.325,49.35 48.405,49.35 J1.10@49.095,50.04
PA_09: J1.7 U1.37 | length 26.5
  Top Layer w0.15: U1.37 40.425,37.85 41.125,38.55 41.125,40.55 41.025,40.65 v1(41.025,42.9)
  Bottom Layer w0.15: v1(41.025,42.9) 41.025,44.75 43.225,46.95 45.925,46.95 47.725,48.75 49.825,48.75 50.125,49.05 55.725,49.05 J1.7@56.715,50.04
PA_10: J1.6 U1.38 | length 28.5
  Top Layer w0.15: U1.38 40.825,37.8 41.425,38.4 41.425,40.95 41.575,41.1 v1(41.575,42.3)
  Bottom Layer w0.15: v1(41.575,42.3) 41.575,44.8 43.425,46.65 46.125,46.65 47.925,48.45 50.025,48.45 50.325,48.75 57.965,48.75 J1.6@59.255,50.04
PA_11: J1.14 U1.40 | length 18.8
  Top Layer w0.15: U1.40 41.625,37.7 42.275,38.35 v1(42.275,39.1)
  Bottom Layer w0.15: J1.14@38.935,50.04 37.025,48.13 37.025,41.95 37.325,41.65 39.575,41.65 40.825,40.4 40.825,39.5 41.225,39.1 v1(42.275,39.1)
PA_12: J1.15 U1.41 | length 20.9
  Top Layer w0.15: U1.41 42.025,37.65 42.825,38.45 v1(42.825,39.65)
  Bottom Layer w0.15: J1.15@36.395,50.04 36.395,48.08 36.725,47.75 36.725,41.75 37.125,41.35 39.425,41.35 40.525,40.25 40.525,39.35 41.325,38.55 42.625,38.55 42.825,38.75 v1(42.825,39.65)
PA_13: J1.16 U1.42 | length 22.1
  Top Layer w0.15: U1.42 42.425,37.6 43.375,38.55 v1(43.375,39.1)
  Bottom Layer w0.15: J1.16@33.855,50.04 36.425,47.47 36.425,41.55 36.925,41.05 39.275,41.05 40.225,40.1 40.225,39.2 41.175,38.25 42.925,38.25 43.375,38.7 v1(43.375,39.1)
PA_14: J1.17 U1.43 | length 26.6
  Top Layer w0.15: U1.43 42.825,37.55 43.925,38.65 v1(43.925,39.65)
  Bottom Layer w0.15: J1.17@31.315,50.04 32.405,48.95 34.425,48.95 36.125,47.25 36.125,41.35 36.725,40.75 39.125,40.75 39.925,39.95 39.925,39.05 41.025,37.95 43.225,37.95 43.925,38.65 v1(43.925,39.65)
PB_00: J2.2 U1.45 | length 20.1
  Top Layer w0.15: J2.2@26.235,32.26 27.325,33.35 31.925,33.35 32.825,34.25 43.125,34.25 43.625,34.75 U1.45
PB_01: J2.4 U1.46 | length 15.5
  Top Layer w0.15: J2.4@31.315,32.26 33.005,33.95 43.325,33.95 44.025,34.65 U1.46
PB_02: J2.1 U1.47 | length 23.6
  Top Layer w0.15: v1(33.136,33.339) 33.125,33.35 33.425,33.65 43.525,33.65 44.425,34.55 U1.47
  Bottom Layer w0.15: J2.1@23.695,32.26 24.774,33.339 v1(33.136,33.339)
PB_03: J2.5 U1.48 | length 13.9
  Top Layer w0.15: J2.5@33.855,32.26 34.945,33.35 43.725,33.35 44.825,34.45 U1.48
PC_00: J1.4 U1.53 | length 27.1
  Top Layer w0.15: U1.53 47.725,39.25 48.625,38.35 51.025,38.35 51.725,39.05 51.725,41.55 51.728,41.547 v1(51.728,41.535)
  Bottom Layer w0.15: v1(51.728,41.535) 51.728,42.053 52.225,42.55 52.225,43.25 52.625,43.65 56.925,43.65 58.225,44.95 61.625,44.95 62.125,45.45 62.125,47.83 J1.4@64.335,50.04
PC_01: J1.5 U1.54 | length 27.9
  Top Layer w0.15: U1.54 47.825,39.65 48.825,38.65 50.825,38.65 51.125,38.95 v1(51.125,40.95)
  Bottom Layer w0.15: v1(51.125,40.95) 51.125,41.95 51.925,42.75 51.925,45.85 52.325,46.25 59.025,46.25 60.025,45.25 61.425,45.25 61.795,45.62 J1.5@61.795,50.04
PC_02: J1.1 U1.55 | length 33.3
  Top Layer w0.15: U1.55 v1(48.225,40.05)
  Bottom Layer w0.15: v1(48.225,40.05) 51.525,40.05 52.925,38.65 54.125,38.65 54.625,39.15 54.625,40.35 58.625,44.35 62.025,44.35 62.725,45.05 62.725,47.45 63.925,48.65 70.565,48.65 J1.1@71.955,50.04
PC_03: J1.2 U1.56 | length 29
  Top Layer w0.15: U1.56 47.425,40.45 v1(47.625,40.65)
  Bottom Layer w0.15: v1(47.625,40.65) 48.525,40.65 48.825,40.35 51.525,40.35 52.325,41.15 54.925,41.15 58.425,44.65 61.825,44.65 62.425,45.25 62.425,47.65 63.725,48.95 68.325,48.95 J1.2@69.415,50.04
PC_04: J2.7 U1.57 | length 15.7
  Top Layer w0.15: v1(44.775,40.85) U1.57
  Bottom Layer w0.15: J2.7@38.935,32.26 38.935,33.64 38.525,34.05 38.525,36.55 39.025,37.05 43.825,37.05 45.125,38.35 45.125,40.15 44.775,40.5 v1(44.775,40.85)
PC_05: J2.6 U1.58 | length 17.6
  Top Layer w0.15: v1(44.225,41.4) 45.025,41.4 45.175,41.25 U1.58
  Bottom Layer w0.15: J2.6@36.395,32.26 38.225,34.09 38.225,36.75 38.825,37.35 43.625,37.35 44.825,38.55 44.825,40 44.225,40.6 v1(44.225,41.4)
PC_08: J2.12 U1.1 | length 17.3
  Top Layer w0.15: v1(44.625,43.45) 44.825,43.65 U1.1
  Bottom Layer w0.15: v1(44.625,43.45) 44.625,43.15 46.325,41.45 46.325,34.75 47.525,33.55 50.345,33.55 J2.12@51.635,32.26
PC_09: J2.11 U1.2 | length 15.5
  Top Layer w0.15: v1(44.075,42.9) 44.075,43.65 44.425,44 U1.2
  Bottom Layer w0.15: v1(44.075,42.9) 44.425,42.9 46.025,41.3 46.025,34.55 47.325,33.25 48.105,33.25 J2.11@49.095,32.26
PC_12: J2.9 U1.5 | length 15.9
  Top Layer w0.15: U1.5 43.225,44 43.525,43.7 v1(43.525,43.45) ; J2.9@44.015,32.26 44.015,33.14 44.525,33.65 v1(46.025,33.65)
  Bottom Layer w0.15: v1(43.525,43.45) 43.525,42.65 43.925,42.25 44.625,42.25 45.725,41.15 45.725,33.95 v1(46.025,33.65)
PC_13: J2.14 U1.6 | length 25.8
  Top Layer w0.15: U1.6 42.825,43.85 42.975,43.7 v1(42.975,42.9)
  Bottom Layer w0.15: v1(42.975,42.9) 42.975,43.7 43.275,44 44.875,44 45.175,43.7 45.175,43.05 46.625,41.6 46.625,34.95 47.725,33.85 50.525,33.85 51.125,33.25 55.725,33.25 J2.14@56.715,32.26
PC_14: J2.15 U1.7 | length 28
  Top Layer w0.15: v1(42.425,43.45) U1.7
  Bottom Layer w0.15: v1(42.425,43.45) 42.425,43.8 42.925,44.3 45.025,44.3 45.475,43.85 45.475,43.2 46.925,41.75 46.925,35.15 47.925,34.15 50.725,34.15 51.325,33.55 57.965,33.55 J2.15@59.255,32.26
POE: D2.2 J5.1 J5.2 | length 8.1
  Top Layer w1: J5.1 J5.2 ccw(c54.344,42.643) 53.635,41.938 54.133,41.439 54.633,40.94 54.925,40.648 54.925,38.85 55.475,38.3 D2.2
REGOUT: C26.2 C27.2 U5.28 | length 5.1
  Top Layer w0.25: C26.2 23.725,42.15 24.025,41.85 U5.28
  Top Layer w0.5: C26.2 22.325,43.424 C27.2
RSTn: C22.1 J2.10 R17.2 SW1.2 U1.28 U5.32 | length 81.1
  Top Layer w0.15: U5.32 24.925,40.25 23.425,38.75 23.425,33.75 23.825,33.35 26.825,33.35 27.125,33.65 31.725,33.65 32.525,34.45 32.525,38.05 32.925,38.45 35.125,38.45 35.925,39.25 U1.28 38.675,39.25 v1(38.825,39.1) ; J2.10@46.555,32.26 49.825,35.53 v1(49.825,36.15) ; R17.2 C22.1 59.525,48.15 59.925,47.75 SW1.2 59.925,45.55 60.325,45.15 v1(60.325,43.75)
  Bottom Layer w0.15: v1(38.825,39.1) 39.425,39.1 40.875,37.65 43.425,37.65 44.525,38.75 44.525,39.85 43.625,40.75 43.625,41.65 43.925,41.95 44.475,41.95 45.425,41 45.425,33.39 J2.10@46.555,32.26 ; v1(49.825,36.15) 54.125,36.15 54.525,36.55 54.525,38.55 54.925,38.95 54.925,40.15 58.525,43.75 v1(60.325,43.75)
RXC: U1.17 U5.14 | length 15.3
  Top Layer w0.15: U5.14 30.625,42.25 31.325,42.95 31.325,44.15 30.925,44.55 30.925,46.45 31.625,47.15 35.625,47.15 36.025,46.75 36.025,44.05 36.425,43.65 U1.17
RXD0: U1.13 U5.18 | length 16.6
  Top Layer w0.15: U5.18 28.825,46.35 30.825,48.35 36.425,48.35 37.925,46.85 39.075,46.85 40.025,45.9 U1.13
RXD1: U1.14 U5.17 | length 15.5
  Top Layer w0.15: U5.17 29.225,46.25 31.025,48.05 36.225,48.05 37.725,46.55 38.925,46.55 39.625,45.85 U1.14
RXD2: U1.15 U5.16 | length 15.6
  Top Layer w0.15: U5.16 30.525,43.05 30.725,43.25 30.725,43.75 30.325,44.15 30.325,46.85 31.225,47.75 36.025,47.75 37.525,46.25 38.775,46.25 39.225,45.8 U1.15
RXD3: U1.16 U5.15 | length 15.1
  Top Layer w0.15: U5.15 30.575,42.65 31.025,43.1 31.025,43.95 30.625,44.35 30.625,46.65 31.425,47.45 35.825,47.45 37.325,45.95 38.625,45.95 38.825,45.75 U1.16
RXDV: U1.12 U5.19 | length 17.8
  Top Layer w0.15: U5.19 28.425,46.45 30.625,48.65 36.625,48.65 38.125,47.15 39.225,47.15 40.425,45.95 U1.12
SWCLK: J3.1 U1.49 | length 27.7
  Top Layer w0.15: U1.49 47.225,37.65 47.525,37.35 v1(47.525,35.55)
  Bottom Layer w0.15: v1(47.525,35.55) 48.425,35.55 48.725,35.25 63.325,35.25 64.325,36.25 69.725,36.25 J3.1
SWDIO: J3.3 U1.50 | length 22.4
  Top Layer w0.15: U1.50 47.325,38.05 47.825,37.55 47.825,36.55 48.125,36.25 v1(48.125,34.95)
  Bottom Layer w0.15: v1(48.125,34.95) 63.525,34.95 63.725,35.15 J3.3
TXC: U1.19 U5.10 | length 8.6
  Top Layer w0.15: U5.10 31.125,40.65 31.225,40.55 34.075,40.55 36.375,42.85 U1.19
TXD0: U1.20 U5.9 | length 8.5
  Top Layer w0.15: U5.9 30.173,40.25 34.225,40.25 36.425,42.45 U1.20
TXD1: U1.21 U5.8 | length 9.4
  Top Layer w0.15: U5.8 30.775,39.5 31.225,39.95 34.375,39.95 36.475,42.05 U1.21
TXD2: U1.22 U5.7 | length 10.6
  Top Layer w0.15: U5.7 28.825,38.95 29.025,38.75 30.525,38.75 31.425,39.65 34.525,39.65 36.525,41.65 U1.22
TXD3: U1.23 U5.6 | length 11.2
  Top Layer w0.15: U5.6 28.425,38.85 28.825,38.45 30.725,38.45 31.625,39.35 34.675,39.35 36.575,41.25 U1.23
TXEN: U1.24 U5.5 | length 11.7
  Top Layer w0.15: U5.5 28.025,38.75 28.625,38.15 30.925,38.15 31.825,39.05 34.825,39.05 36.625,40.85 U1.24
U_RXD2: U1.4 U3.6 | length 22.2
  Top Layer w0.15: U1.4 43.675,44.925 43.675,45.824 44.001,46.15 45.401,46.15 47.901,48.65 51.649,48.65 52.125,48.174 52.125,46.85 52.425,46.55 54.349,46.55 54.825,46.074 54.825,43.45 55.975,42.3 57.375,42.3 57.86,42.785 U3.6
U_TXD2: U1.3 U3.7 | length 21.7
  Top Layer w0.15: U1.3 43.975,44.925 43.975,45.7 44.125,45.85 45.525,45.85 48.025,48.35 51.525,48.35 51.825,48.05 51.825,46.726 52.301,46.25 54.225,46.25 54.525,45.95 54.525,43.326 55.851,42 57.375,42 57.86,41.515 U3.7
USB_D_N: R11.2 U3.2 | length 9.4
  Top Layer w0.15: v1(62.625,41.515) U3.2 ; v1(65.625,40.325) R11.2
  Bottom Layer w0.15: v1(62.625,41.515) 63.11,41.03 63.881,41.03 65.101,42.25 66.349,42.25 66.725,41.874 66.725,41.026 66.374,40.675 65.975,40.675 v1(65.625,40.325)
USB_D_P: R13.2 U3.1 | length 8.4
  Top Layer w0.15: v1(62.625,40.245) U3.1 ; v1(65.625,41.325) R13.2
  Bottom Layer w0.15: v1(62.625,40.245) 63.11,40.73 64.005,40.73 65.225,41.95 66.225,41.95 66.425,41.75 66.425,41.15 66.25,40.975 65.975,40.975 v1(65.625,41.325)
USER_LED: LD2.2 U1.8 | length 29
  Top Layer w0.15: U1.8 42.025,45.75 42.825,46.55 45.025,46.55 47.525,49.05 66.925,49.05 67.525,48.45 LD2.2
VBUS: D1.2 J2.20 P2.1 | length 12.5
  Top Layer w0.8: D1.2 67.275,37.3 67.925,36.65 71.725,36.65 72.325,36.05 72.325,34.15 71.955,33.78 71.955,32.26 J2.20@71.955,30.65
VC1: J4.1 J4.2 P1.R9 | length 12.2
  Top Layer w0.5: P1.R9 16.43,36.755 17.225,37.55 17.225,40.945 J4.2 J4.1
VC2: J4.3 J4.4 P1.R10 | length 11.2
  Top Layer w0.5: P1.R10 16.845,35.485 J4.4 J4.3
VDD_3.3A: C14.2 C15.2 L1.2 U5.31 | length 7.6
  Top Layer w0.25: C14.2 22.925,39.15 24.425,40.65 U5.31
  Top Layer w0.5: C14.2 22.325,37.876 C15.2
  Top Layer w0.8: C15.2 22.625,37.576 L1.2
VDD_3.3V: C5.2 C8.2 C9.2 C10.2 C11.2 C12.2 C13.2 C24.2 C25.2 C28.2 C29.2 J2.16 L1.1 R5.1 R7.1 R12.1 R17.1 R18.2 R19.2 R20.2 R21.2 SW2.1 U1.10 U1.61 U2.5 U3.5 U3.8 U5.13 | length 36.6
  Top Layer w0.25: U5.13 30.825,41.85 32.125,43.15 C25.2 ; C13.2 40.725,46.65 41.225,46.15 U1.10 ; U1.61 47.025,42.45 48.325,41.15 C12.2
  Top Layer w0.5: R7.1 R5.1 v1(18.225,49.65) ; R19.2 v1(26.325,47.45) ; v1(31.525,45.275) 32.322,45.275 C24.2 32.825,45.424 C29.2 C25.2 ; R18.2 R20.2 v1(34.725,42.15) ; C13.2 C28.2 42.799,47.35 C10.2 43.077,47.715 ccw(c42.624,47.928) 43.106,47.796 ccw(c42.624,47.928) 43.122,47.879 v1(43.2,48.675) ; v1(49.325,39.35) C11.2 C12.2 ; v1(52.725,47.15) R17.1 ; v1(56.825,44.85) C8.2 58.552,44.05 U3.5 ; R12.1 57.525,38.95 v1(57.025,39.45) C9.2 57.03,40.245 U3.8 ; U2.5 61.85,34.65 C5.2 ; v1(66.325,45.35) SW2.1 ; R21.2 v1(68.825,47.95)
  Top Layer w0.8: v1(18.725,35.05) 18.851,35.177 ccw(c18.283,35.741) 18.859,35.186 18.86,35.187 cw(c19.438,34.633) v1@18.866,35.193 ; v1@18.867,35.193 ccw(c18.295,35.754) 18.97,35.323 ; 18.97,35.324 cw(c19.645,34.895) 19.021,35.395 v1(19.225,35.65) v1(19.91,35.65) 20.495,35.65
  other v1: 62.925,33.25 63.625,33.25 62.925,33.95 63.625,33.95 31.525,45.95 42.625,48.675
VSYS: C4.2 D1.1 D2.1 J2.19 R14.1 U2.1 | length 34.2
  Top Layer w0.15: R14.1 v1(58.525,38.85)
  Top Layer w0.5: U2.1 61.775,37.7 61.625,37.85 v1(61.625,38.85) 61.625,39.15 61.925,39.45 63.125,39.45 63.425,39.15 C4.2 D1.1
  Top Layer w0.8: v1(64.625,36.95) 64.325,36.65 64.325,34.65 65.225,33.75 68.825,33.75 69.415,33.16 69.415,32.26 J2.19@69.415,30.65
  Bottom Layer w0.15: v1(58.525,38.85) 58.525,39.95 59.025,40.45 61.025,40.45 61.625,39.85 v1(61.625,38.85)
  Bottom Layer w0.8: v1(55.425,37.15) v1(56.113,37.15) v1(56.765,37.15) 57.725,37.15 58.875,36 61.475,36 62.825,37.35 64.975,37.35
  other v1: 65.325,36.95 64.625,37.65 65.325,37.65
X1: C19.2 U5.2 Y3.3 | length 7.2
  Top Layer w0.25: C19.2 25.425,35.15 Y3.3 26.625,34.85 26.825,35.05 U5.2
X2: C18.2 U5.3 Y3.1 | length 4.9
  Top Layer w0.25: U5.3 27.225,37.05 27.825,36.45 Y3.1 28.225,36.15 C18.2
XIN: C17.2 R15.2 U1.63 Y2.3 | length 8.6
  Top Layer w0.25: U1.63 47.025,43.25 47.525,43.75 47.525,44.95 R15.2 50.425,45.25 50.575,45.1 Y2.3 50.325,43.95 C17.2
XOUT: C16.2 R15.1 U1.64 Y2.1 | length 6.5
  Top Layer w0.25: U1.64 46.825,43.65 47.125,43.95 47.125,45.55 R15.1 49.025,46.25 Y2.1 49.325,46.55 C16.2
pads on no net: P1.0 P1.R8 P2.4 U1.59 U1.60 U3.4 U5.1 U5.21

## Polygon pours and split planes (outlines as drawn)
GND on Bottom Layer "GND" (solid, remove dead copper, pour order 1): 15.325,35.15 15.825,34.65 19.325,34.65 19.825,34.15 19.825,31.65 20.325,31.15 72.825,31.15 72.825,51.15 15.825,51.15 15.325,50.65
GND on Top Layer "GND" (solid, remove dead copper, pour order 0): 15.325,35.15 15.825,34.65 19.325,34.65 19.825,34.15 19.825,31.65 20.325,31.15 72.825,31.15 72.825,51.15 15.825,51.15 15.325,50.65
VDD_3.3V on Internal Plane 2 (split plane): 72.815,31.16 17.825,31.16 17.825,34.65 15.325,34.65 15.325,38.15 15.325,40.65 15.325,51.14 72.815,51.14
GND on Internal Plane 1 (split plane): 72.815,31.16 17.825,31.16 17.825,34.65 15.325,34.65 15.325,38.15 12.325,38.15 12.325,40.65 15.325,40.65 15.325,51.14 72.815,51.14

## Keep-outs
Keep-Out Layer:
  the board outline again, w0.15
  text ".Layer_Name" at 7.723,57.15 h1.52

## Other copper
Top Layer:
  rectangle net VSYS: 55.025,35.5 57.125,37.45
  rectangle net VDD_3.3V: 31.225,44.936 32.825,46.328
  rectangle net VDD_3.3V: 42.262,47.35 43.527,49.05
  region net VSYS: 64.225,36.85 64.525,36.55 65.425,36.55 65.725,36.85 65.725,38.85 65.425,39.15 64.525,39.15 64.225,38.85
  region net VDD_3.3V: 62.825,32.95 62.625,33.15 62.625,34.35 61.525,34.35 61.525,34.95 63.725,34.95 63.725,34.35 63.925,34.15 63.925,33.15 63.725,32.95
  region net VBUS: 67.025,37.75 67.625,37.75 67.85,37.975 67.85,38.675 68.8,39.625 69.905,39.625 69.905,40.075 67.85,40.075 66.925,39.15 66.725,39.15 66.725,38.05
  text ".Layer_Name" at 7.723,57.15 h1.52
Bottom Layer:
  region net VSYS: 64.425,38.05 65.425,38.05 65.725,37.75 65.725,36.85 65.425,36.55 64.525,36.55 64.025,37.05 64.025,37.65
  text ".Layer_Name" at 7.723,57.15 h1.52
Internal Plane 1 (plane layer: these items are gaps in the copper):
  region: -1.675,51.65 15.325,51.65 15.325,40.65 12.325,40.65 12.325,38.15 15.325,38.15 15.325,34.65 17.825,34.65 17.825,30.65 -1.675,30.65
Internal Plane 2 (plane layer: these items are gaps in the copper):
  rectangle: 24.825,34.05 28.825,37.25
  rectangle: 48.325,43.35 51.325,47.15
  region: -1.675,51.65 15.325,51.65 15.325,40.65 15.325,38.15 15.325,34.65 17.825,34.65 17.825,30.65 -1.675,30.65

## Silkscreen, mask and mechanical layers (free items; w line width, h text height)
Top Overlay:
  circle w0.15: c64.125,39.65 r0.103
  circle w0.15: c61.725,38.15 r0.103
  circle w0.15: c44.825,46.15 r0.103
  region: 67.525,46.9 67.925,46.4 67.125,46.4
  region: 58.125,34.9 57.725,35.4 58.525,35.4
  region: 56.125,36.9 55.725,37.4 56.525,37.4
  region: 65.875,38.65 66.375,39.05 66.375,38.25
  lines w0.15: 55.725,36.9 56.525,36.9 ; 57.725,34.9 58.525,34.9 ; 65.875,38.25 65.875,39.05 ; 67.125,46.9 67.925,46.9 ; 55.725,37.4 56.125,36.9 56.525,37.4 55.725,37.4 ; 57.725,35.4 58.125,34.9 58.525,35.4 57.725,35.4 ; 65.875,38.65 66.375,38.25 66.375,39.05 65.875,38.65 ; 67.125,46.4 67.925,46.4 67.525,46.9 67.125,46.4
  text ".Layer_Name" at 7.723,57.182 h1.52
  text "Rev.1.0" at -1.375,50.25 h1.5
  text "RESET" at 56.025,48.3 h0.7
  text "BOOT" at 62.925,48.3 h0.7
  text "Surf5" at -1.425,30.9 h1.5
  text "Made by WIZnet" at 2.6,30.65 h1.5
Bottom Overlay:
  text ".Layer_Name" at 7.723,57.15 h1.52
  text "GND" at 28.386,46.37 h1.2 r270
  text "GND" at 41.086,46.37 h1.2 r270
  text "GND" at 53.786,46.37 h1.2 r270
  text "GND" at 66.486,46.37 h1.2 r270
  text "PA01" at 23.311,46.219 h1.2 r270
  text "PA11" at 38.544,46.219 h1.2 r270
  text "PC01" at 61.406,46.219 h1.2 r270
  text "PC03" at 69.036,46.1 h1.2 r270
  text "PC02" at 71.536,46.108 h1.2 r270
  text "PA00" at 25.851,46.097 h1.2 r270
  text "PA13" at 33.471,46.09 h1.2 r270
  text "PA12" at 36.004,46.098 h1.2 r270
  text "PA05" at 43.631,46.076 h1.2 r270
  text "PA07" at 46.171,46.091 h1.2 r270
  text "PA08" at 48.711,46.091 h1.2 r270
  text "PA06" at 51.251,46.082 h1.2 r270
  text "PA09" at 56.331,46.094 h1.2 r270
  text "PA10" at 58.871,46.097 h1.2 r270
  text "PC00" at 63.946,46.097 h1.2 r270
  text "PA14" at 30.924,46.068 h1.2 r270
  text "VC1" at 17.637,44.565 h1.2
  text "POE" at 52.259,44.566 h1.2
  text "VC1" at 17.637,42.025 h1.2
  text "POE" at 52.259,42.026 h1.2
  text "VC2" at 17.758,39.485 h1.2
  text "GND" at 52.405,39.486 h1.2
  text "VC1" at 17.637,36.945 h1.2
  text "GND" at 52.405,36.946 h1.2
  text "SWDIO" at 65.741,36.094 h1.2 r270
  text "GND" at 67.841,36.07 h1.2 r270
  text "SWCLK" at 69.641,36.055 h1.2 r270
  text "PB02" at 23.316,34.01 h1.2 r270
  text "PB00" at 25.856,34.01 h1.2 r270
  text "GND" at 28.391,34.01 h1.2 r270
  text "PB01" at 30.936,34.01 h1.2 r270
  text "PB03" at 33.476,34.01 h1.2 r270
  text "PC05" at 36.011,34.01 h1.2 r270
  text "PC04" at 38.551,34.01 h1.2 r270
  text "GND" at 41.091,34.01 h1.2 r270
  text "PC12" at 43.63,34.01 h1.2 r270
  text "RSTn" at 46.171,34.01 h1.2 r270
  text "PC09" at 48.711,34.01 h1.2 r270
  text "PC08" at 51.251,34.01 h1.2 r270
  text "GND" at 53.791,34.01 h1.2 r270
  text "PC13" at 56.331,34.01 h1.2 r270
  text "PC14" at 58.87,34.01 h1.2 r270
  text "3V3" at 61.416,34.01 h1.2 r270
  text "3V3_EN" at 64.055,34.01 h1.2 r270
  text "VBUS" at 72.141,33.65 h1.2 r270
  text "GND" at 67.625,33.366 h1.2
  text "VSYS" at 70.825,33.366 h1.2
Top Paste:
  text ".Layer_Name" at 7.723,57.15 h1.52
Bottom Paste:
  text ".Layer_Name" at 7.723,57.15 h1.52
Top Solder:
  text ".Layer_Name" at 7.723,57.15 h1.52
Bottom Solder:
  text ".Layer_Name" at 7.723,57.15 h1.52
Drill Guide:
  text ".Layer_Name" at 7.723,57.15 h1.52
Mechanical 2:
  lines w0.127: 80.894,35.775 80.894,59.856 ; 80.895,35.816 ccw(c81.606,35.816) 81.606,35.105 119.358,35.105 ccw(c119.358,35.816) 120.069,35.816 ; 80.895,59.881 cw(c81.606,59.881) 81.606,60.592 119.358,60.592 cw(c119.358,59.881) 120.069,59.881 120.069,35.8 ; 82.419,52.085 119.325,52.085 ; 82.419,54.56 119.325,54.56
  lines w0.15: -1.675,30.65 -1.675,51.65 73.325,51.65 73.325,30.65 -1.675,30.65
  text "BOARD NAME : Surf5" at -1.675,68.326 h1.52
  text "VERSION : R110" at -1.675,65.532 h1.52
  text "SIZE : 75mmX21mmX1.6T" at -1.675,62.738 h1.52
  text "GERBER DATE : 2023.11.03" at -1.675,59.944 h1.52
  text "Layer Stack Up Detail for :" at 82.419,58.357 h1.02
  text "LAYER :" at -1.675,57.15 h1.52
  text "Surf5_R110.PcbDoc" at 82.419,55.817 h1.27
  text "Layer Name : 4L 1.6T" at 82.419,52.769 h1.02
  text "Top Layer" at 82.419,46.911 h1.52
  text "Internal Plane 1 (GND)" at 82.419,43.863 h1.52
  text "Internal Plane 2 (PWR)" at 82.419,40.767 h1.52
  text "Bottom Layer" at 82.419,37.719 h1.52
  text "KS Technology artwork" at 80.825,30.65 h5.08
Mechanical 3:
  lines w0.1: 57.075,38.8 57.075,36.5 57.375,36.5 57.375,33.5 59.125,33.5 59.125,38.85 57.125,38.85 ; 36.625,46.15 38.925,46.15 38.925,48.25 36.625,48.25 36.625,46.15
  lines w0.15: 38.925,48.25 39.025,48.25 ; 39.125,46.75 38.959,46.916 38.959,46.95 ; 39.125,47.15 38.959,46.984 38.959,46.95 ; 40.325,46.95 38.959,46.95 ; 52.525,34.45 52.247,34.728 52.229,34.728 ; 57.375,34.728 52.229,34.728 ; 52.229,34.728 52.525,35.024 52.229,34.728 ; 50.125,34.543 50.125,36.65 50.425,36.65 52.225,36.65 52.225,34.55 51.925,34.55 51.925,33.15 50.625,33.15 50.625,34.55 50.132,34.55 50.125,34.543
Drill Drawing:
  text ".Legend" at 82.585,62.15 h1.02
  text ".Layer_Name" at 7.723,57.15 h1.52

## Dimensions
73.325,30.65 to 73.325,51.65 on Mechanical 2
-1.675,30.65 to 73.325,30.65 on Mechanical 2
